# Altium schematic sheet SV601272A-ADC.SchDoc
size 431 x 279 mm; Date: Not shown in title block; ApprovedBy: Not shown in title block; CheckedBy: Not shown in title block; Author: Not shown in title block; CompanyName: Not shown in title block; Engineer: Not shown in title block; Organization: Not shown in title block; Address1: Not shown in title block; Address2: Not shown in title block; Address3: Not shown in title block; Address4: Not shown in title block; DocumentNumber: 9; Revision: Use project parameter SCH_Rev; SheetNumber: 9; SheetTotal: 11; PageSetup: Record=PageOptions¦CenterHorizontal=True¦CenterVertical=True¦PrintScale=1.00¦XCorrection=1.00¦YCorrection=1.00¦PrintKind=0¦BorderSize=5000000¦LeftOffset=0¦BottomOffset=0¦Orientation=2¦PaperLength=1000¦PaperWidth=1000¦Scale=100¦PaperSource=15¦PrintQuality=600¦MediaType=1¦DitherType=10¦PaperKind=Letter¦PrintScaleMode=1
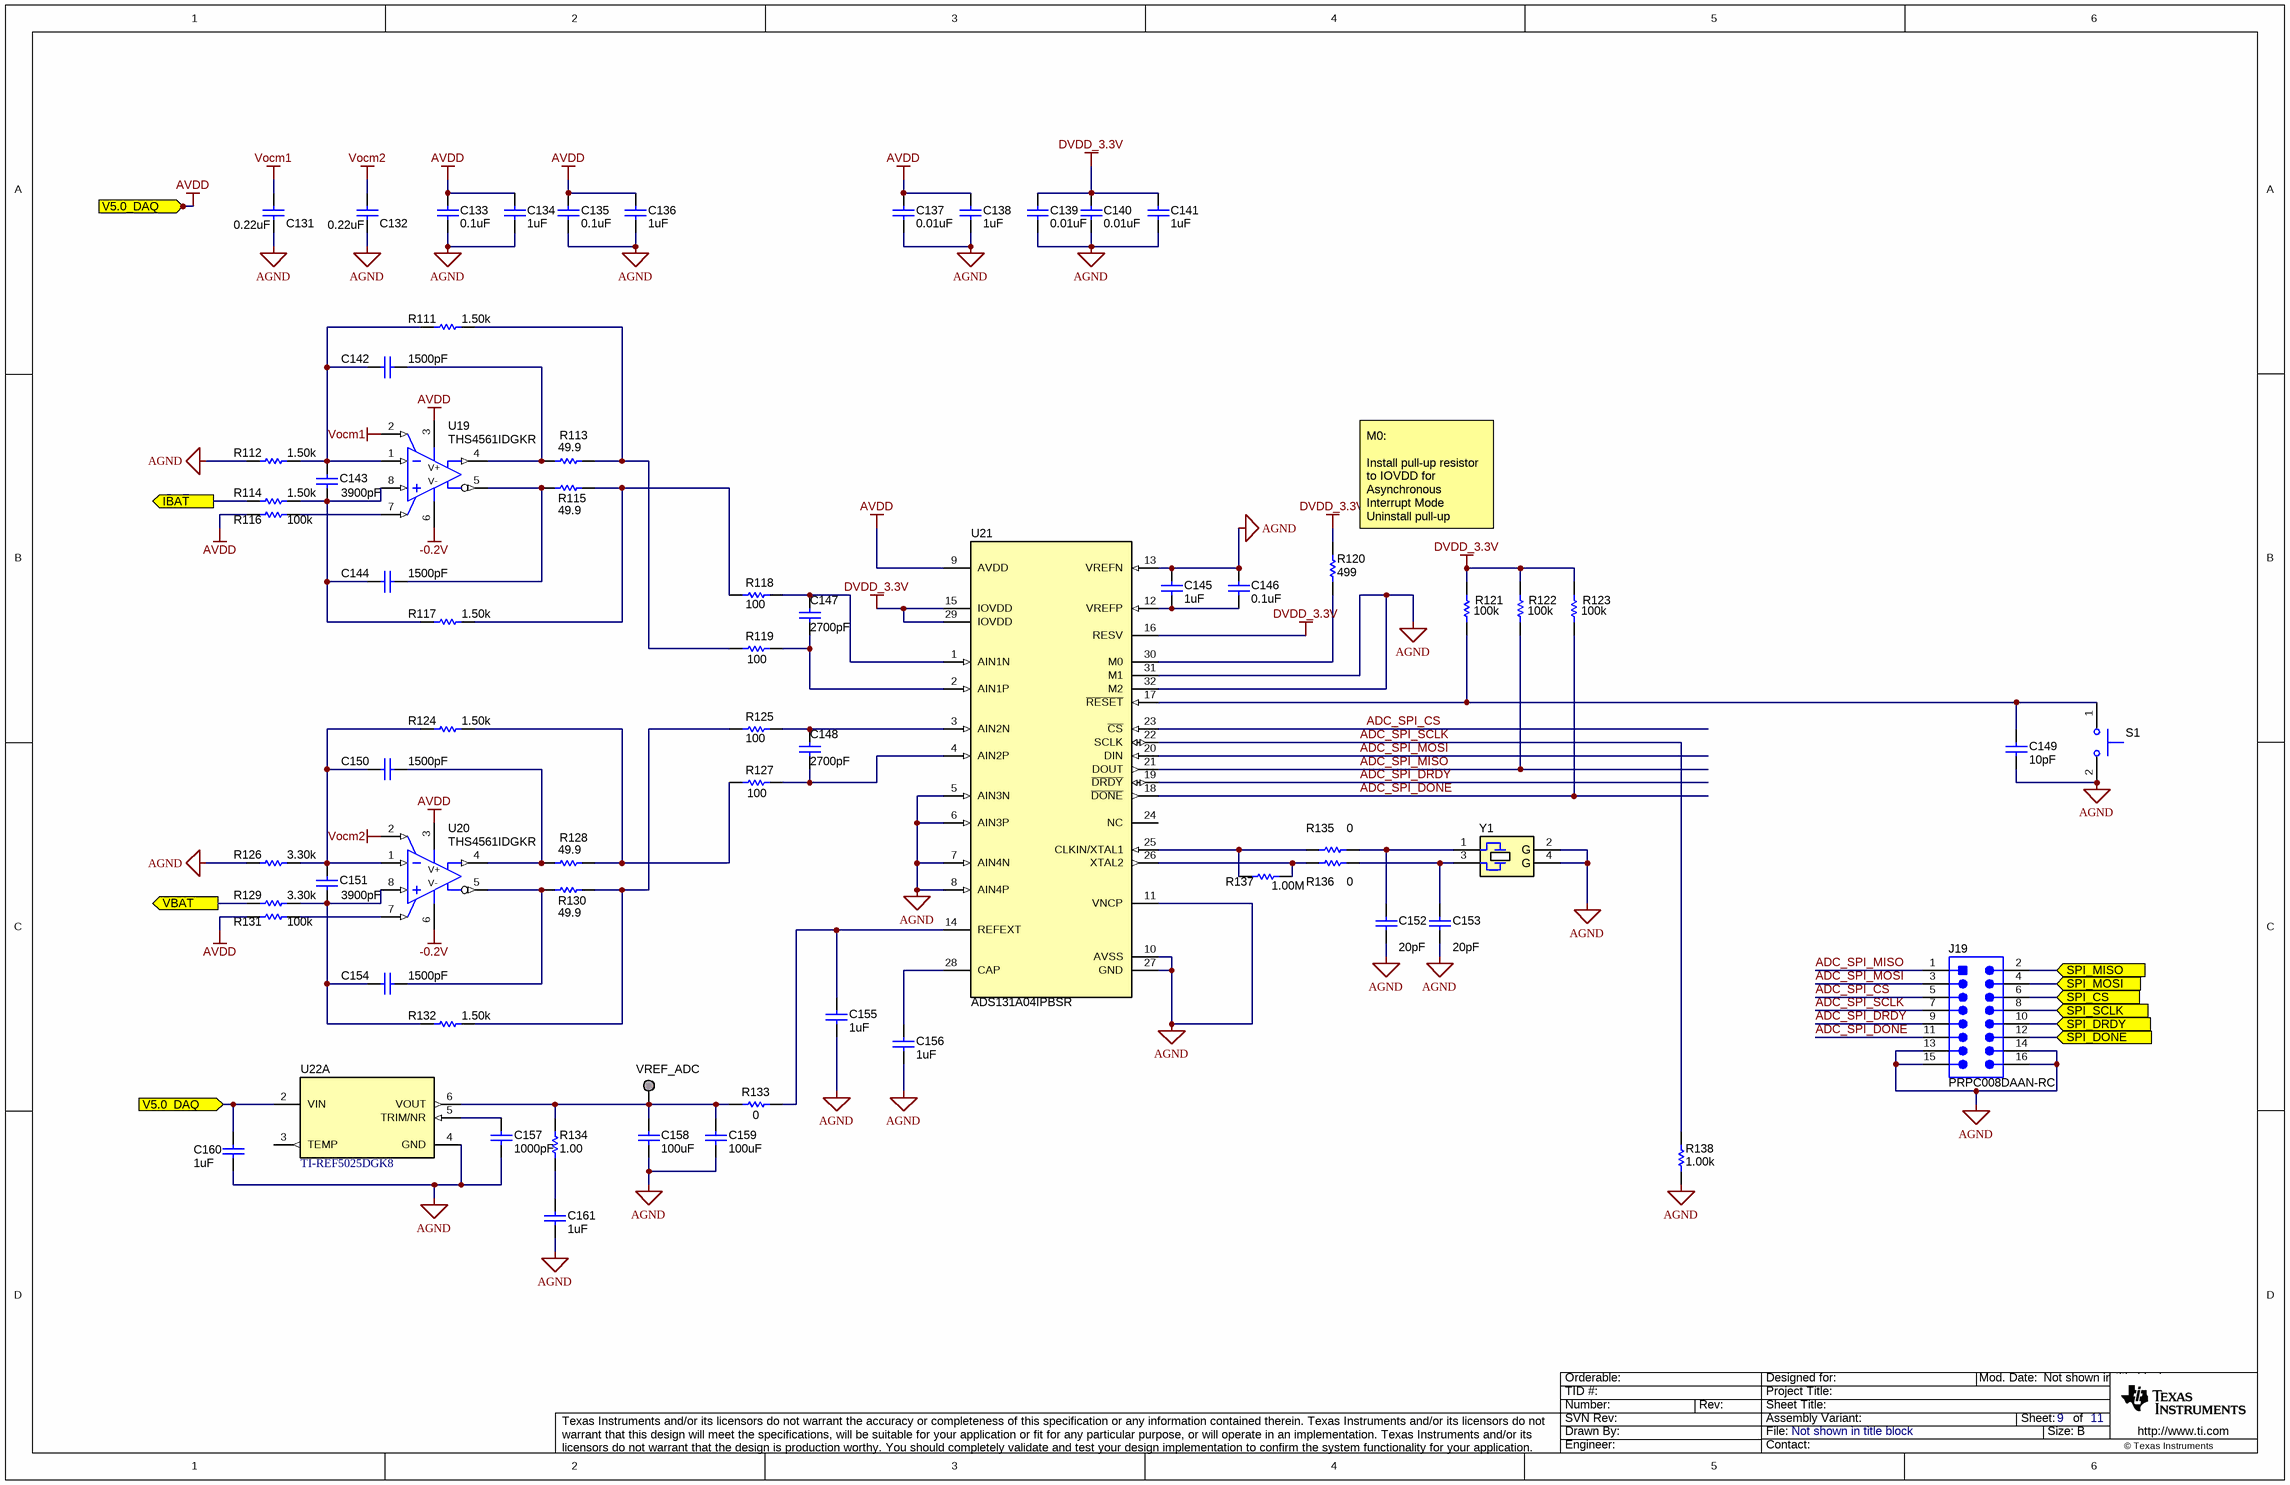
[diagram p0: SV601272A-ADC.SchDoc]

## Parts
C131  ValueDisplayed: 0.22uF  [0603]  (hidden comment: Capacitor)
C132  ValueDisplayed: 0.22uF  [0603]  (hidden comment: Capacitor)
C133  ValueDisplayed: 0.1uF  [0603]  (hidden comment: Capacitor)
C134  ValueDisplayed: 1uF  [0603]  (hidden comment: Capacitor)
C135  ValueDisplayed: 0.1uF  [0603]  (hidden comment: Capacitor)
C136  ValueDisplayed: 1uF  [0603]  (hidden comment: Capacitor)
C137  ValueDisplayed: 0.01uF  [0603]  (hidden comment: Capacitor)
C138  ValueDisplayed: 1uF  [0603]  (hidden comment: Capacitor)
C139  ValueDisplayed: 0.01uF  [0603]  (hidden comment: Capacitor)
C140  ValueDisplayed: 0.01uF  [0603]  (hidden comment: Capacitor)
C141  ValueDisplayed: 1uF  [0603]  (hidden comment: Capacitor)
C142  ValueDisplayed: 1500pF  [0603]  (hidden comment: Capacitor)
C143  ValueDisplayed: 3900pF  [0603]  (hidden comment: GRM188R72A392KA01D)
C144  ValueDisplayed: 1500pF  [0603]  (hidden comment: Capacitor)
C145  ValueDisplayed: 1uF  [0603]  (hidden comment: Capacitor)
C146  ValueDisplayed: 0.1uF  [0603]  (hidden comment: Capacitor)
C147  ValueDisplayed: 2700pF  [0603]  (hidden comment: Capacitor)
C148  ValueDisplayed: 2700pF  [0603]  (hidden comment: Capacitor)
C149  ValueDisplayed: 10pF  [0603]  (hidden comment: Capacitor)
C150  ValueDisplayed: 1500pF  [0603]  (hidden comment: Capacitor)
C151  ValueDisplayed: 3900pF  [0603]  (hidden comment: GRM188R72A392KA01D)
C152  ValueDisplayed: 20pF  [0603]  (hidden comment: GRM1885C1H200JA01D)
C153  ValueDisplayed: 20pF  [0603]  (hidden comment: GRM1885C1H200JA01D)
C154  ValueDisplayed: 1500pF  [0603]  (hidden comment: Capacitor)
C155  ValueDisplayed: 1uF  [0603]  (hidden comment: Capacitor)
C156  ValueDisplayed: 1uF  [0603]  (hidden comment: Capacitor)
C157  ValueDisplayed: 1000pF  [0603]  (hidden comment: Capacitor)
C158  ValueDisplayed: 100uF  [1206_190]  (hidden comment: Capacitor)
C159  ValueDisplayed: 100uF  [1206_190]  (hidden comment: Capacitor)
C160  ValueDisplayed: 1uF  [0603]  (hidden comment: Capacitor)
C161  ValueDisplayed: 1uF  [0603]  (hidden comment: Capacitor)
J19  PRPC008DAAN-RC  [Sullins_xxxC008DAAN]
R111  ValueDisplayed: 1.50k  [0603]  (hidden comment: RC0603FR-071K5L)
R112  ValueDisplayed: 1.50k  [0603]  (hidden comment: RC0603FR-071K5L)
R113  ValueDisplayed: 49.9  [0603]  (hidden comment: Resistor)
R114  ValueDisplayed: 1.50k  [0603]  (hidden comment: RC0603FR-071K5L)
R115  ValueDisplayed: 49.9  [0603]  (hidden comment: Resistor)
R116  ValueDisplayed: 100k  [0603]  (hidden comment: Resistor)
R117  ValueDisplayed: 1.50k  [0603]  (hidden comment: RC0603FR-071K5L)
R118  ValueDisplayed: 100  [0603]  (hidden comment: Resistor)
R119  ValueDisplayed: 100  [0603]  (hidden comment: Resistor)
R120  ValueDisplayed: 499  [0603]  (hidden comment: Resistor)
R121  ValueDisplayed: 100k  [0603]  (hidden comment: Resistor)
R122  ValueDisplayed: 100k  [0603]  (hidden comment: Resistor)
R123  ValueDisplayed: 100k  [0603]  (hidden comment: Resistor)
R124  ValueDisplayed: 1.50k  [0603]  (hidden comment: RC0603FR-071K5L)
R125  ValueDisplayed: 100  [0603]  (hidden comment: Resistor)
R126  ValueDisplayed: 3.30k  [0603]  (hidden comment: RC0603FR-073K3L)
R127  ValueDisplayed: 100  [0603]  (hidden comment: Resistor)
R128  ValueDisplayed: 49.9  [0603]  (hidden comment: Resistor)
R129  ValueDisplayed: 3.30k  [0603]  (hidden comment: RC0603FR-073K3L)
R130  ValueDisplayed: 49.9  [0603]  (hidden comment: Resistor)
R131  ValueDisplayed: 100k  [0603]  (hidden comment: Resistor)
R132  ValueDisplayed: 1.50k  [0603]  (hidden comment: RC0603FR-071K5L)
R133  ValueDisplayed: 0  [0603]  (hidden comment: Resistor)
R134  ValueDisplayed: 1.00  [0603]  (hidden comment: Resistor)
R135  ValueDisplayed: 0  [0603]  (hidden comment: Resistor)
R136  ValueDisplayed: 0  [0603]  (hidden comment: Resistor)
R137  ValueDisplayed: 1.00M  [0603]  (hidden comment: Resistor)
R138  ValueDisplayed: 1.00k  [0603]  (hidden comment: Resistor)
S1  Switch_PushButton  [SW_TL1015AF160QG]  (value not drawn)
U19  THS4561IDGKR  [DGK0008A_N]
U20  THS4561IDGKR  [DGK0008A_N]
U21  ADS131A04IPBSR  [PBS0032A_L]
U22  TI-REF5025DGK8  [DGK0008A_N]  (part A of 2)
VREF_ADC  Pogo Pad  [PogoPad]  (value not drawn)  (no BOM)
Y1  XTAL_4P_13_G24  [CTS_407]  (value not drawn)

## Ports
IBAT, SPI_CS, SPI_DONE, SPI_DRDY, SPI_MISO, SPI_MOSI, SPI_SCLK, V5.0_DAQ, VBAT

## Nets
-0.2V: U19.6(VS-) U20.6(VS-)
AGND: C131.2 C132.2 C133.2 C134.2 C135.2 C136.2 C137.2 C138.2 C139.2 C140.2 C141.2 C145.1 C146.1 C149.1 C152.2 C153.2 C155.2 C156.2 C157.2 C158.2 C159.2 C160.2 C161.2 J19.13 J19.14 J19.15 J19.16 R112.1 R126.1 R138.1 S1.2 U21.5(AIN3N) U21.6(AIN3P) U21.7(AIN4N) U21.8(AIN4P) U21.10(AVSS) U21.11(VNCP) U21.13(VREFN) U21.27(GND) U21.31(M1) U21.32(M2) U22.4(GND) Y1.2(GND) Y1.4(GND)
AVDD: C133.1 C134.1 C135.1 C136.1 C137.1 C138.1 C160.1 R116.2 R131.2 U19.3(VS+) U20.3(VS+) U21.9(AVDD) U22.2(VIN) ; port V5.0_DAQ
DVDD_3.3V: C139.1 C140.1 C141.1 R120.2 R121.2 R122.2 R123.2 U21.15(IOVDD) U21.16(RESV) U21.29(IOVDD)
Vocm1: C131.1 U19.2(VOCM)
Vocm2: C132.1 U20.2(VOCM)
ADC_SPI_CS: J19.5 U21.23(~{CS})
ADC_SPI_DONE: J19.11 R123.1 U21.18(~{DONE})
ADC_SPI_DRDY: J19.9 U21.19(~{DRDY})
ADC_SPI_MISO: J19.1 R122.1 U21.21(DOUT)
ADC_SPI_MOSI: J19.3 U21.20(DIN)
ADC_SPI_SCLK: J19.7 R138.2 U21.22(SCLK)
IBAT: R114.1 ; port IBAT
SPI_CS: J19.6 ; port SPI_CS
SPI_DONE: J19.12 ; port SPI_DONE
SPI_DRDY: J19.10 ; port SPI_DRDY
SPI_MISO: J19.2 ; port SPI_MISO
SPI_MOSI: J19.4 ; port SPI_MOSI
SPI_SCLK: J19.8 ; port SPI_SCLK
VBAT: R129.1 ; port VBAT
NetC142_1: C142.1 C143.1 R111.1 R112.2 U19.1(VIN-)
NetC142_2: C142.2 R113.1 U19.4(VOUT+)
NetC143_2: C143.2 C144.1 R114.2 R117.1 U19.8(VIN+)
NetC144_2: C144.2 R115.1 U19.5(VOUT-)
NetC145_2: C145.2 C146.2 U21.12(VREFP)
NetC147_1: C147.1 R118.2 U21.1(AIN1N)
NetC147_2: C147.2 R119.2 U21.2(AIN1P)
NetC148_1: C148.1 R125.2 U21.3(AIN2N)
NetC148_2: C148.2 R127.2 U21.4(AIN2P)
NetC149_2: C149.2 R121.1 S1.1 U21.17(~{RESET})
NetC150_1: C150.1 C151.1 R124.1 R126.2 U20.1(VIN-)
NetC150_2: C150.2 R128.1 U20.4(VOUT+)
NetC151_2: C151.2 C154.1 R129.2 R132.1 U20.8(VIN+)
NetC152_1: C152.1 R135.2 Y1.1
NetC153_1: C153.1 R136.1 Y1.3
NetC154_2: C154.2 R130.1 U20.5(VOUT-)
NetC155_1: C155.1 R133.2 U21.14(REFEXT)
NetC156_1: C156.1 U21.28(CAP)
NetC157_1: C157.1 U22.5(TRIM/NR)
NetC158_1: C158.1 C159.1 R133.1 R134.2 U22.6(VOUT) VREF_ADC.1
NetC161_1: C161.1 R134.1
NetR111_2: R111.2 R113.2 R119.1
NetR115_2: R115.2 R117.2 R118.1
NetR116_1: R116.1 U19.7(~{PD})
NetR120_1: R120.1 U21.30(M0)
NetR124_2: R124.2 R127.1 R128.2
NetR125_1: R125.1 R130.2 R132.2
NetR131_1: R131.1 U20.7(~{PD})
NetR135_1: R135.1 R137.2 U21.25(CLKIN/XTAL1)
NetR136_2: R136.2 R137.1 U21.26(XTAL2)

Not connected (* = marked no-connect by the designer): U21 24(NC); U22 3(TEMP)

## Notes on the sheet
- (near R120) M0:
  Install pull-up resistor to IOVDD for Asynchronous Interrupt Mode
  Uninstall pull-up resistor to leave M0 floating for Synchronous Slave Mode

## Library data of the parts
C131 C132 = CMP-0006903-4: CAP, CERM, 0.22 uF, 16 V, +/- 10%, X7R, 0603; PartNumber: C0603C224K4RACTU; Manufacturer: Kemet; Polarized: N; Value: 0.22uF; U/M: EA; Cap_F: 220nF; Value1: Unknown; VDC_V: 16V; TaMin_C: -55°C; TaMax_C: 125°C; AEC Category: Q200; SizeArea_mm2: 1.28; SizeAreaWB_mm2: 4.68; SizeX_mm: 1.6; SizeY_mm: 0.8; SizeZ_mm: 1
C133 C135 C146 = CMP-0006752-5: CAP, CERM, 0.1 uF, 25 V, +/- 5%, X7R, 0603; PartNumber: 06033C104JAT2A; Manufacturer: AVX; Polarized: N; Value: 0.1uF; U/M: EA; Cap_F: 100nF; ESR_ohm: 0.05; Value1: 0.05 ohm; VDC_V: 25V; TaMin_C: -55°C; TaMax_C: 125°C; AEC Category: Q200; SizeArea_mm2: 1.28; SizeAreaWB_mm2: 4.68; SizeX_mm: 1.6; SizeY_mm: 0.8; SizeZ_mm: 1
C134 C136 C138 C141 C145 C155 C156 C160 C161 = CMP-0007405-4: CAP, CERM, 1 uF, 25 V, +/- 10%, X7R, 0603; PartNumber: GRM188R71E105KA12D; Manufacturer: MuRata; Polarized: N; Value: 1uF; U/M: EA; Cap_F: 1µF; Value1: Unknown; VDC_V: 25V; TaMin_C: -55°C; TaMax_C: 125°C; AEC Category: Q200; SizeArea_mm2: 1.28; SizeAreaWB_mm2: 4.68; SizeX_mm: 1.6; SizeY_mm: 0.8; SizeZ_mm: 1
C137 C139 C140 = CMP-0006727-4: CAP, CERM, 0.01 uF, 100 V, +/- 10%, X7R, 0603; PartNumber: 06031C103KAT2A; Manufacturer: AVX; Polarized: N; Value: 0.01uF; U/M: EA; Cap_F: 10nF; ESR_ohm: 0.098; Value1: 0.098 ohm; VDC_V: 100V; TaMin_C: -55°C; TaMax_C: 125°C; AEC Category: Q200; SizeArea_mm2: 1.28; SizeAreaWB_mm2: 4.68; SizeX_mm: 1.6; SizeY_mm: 0.8; SizeZ_mm: 1
C142 C144 C150 C154 = CMP-0006732-4: CAP, CERM, 1500 pF, 100 V, +/- 5%, X7R, 0603; PartNumber: 06031C152JAT2A; Manufacturer: AVX; Polarized: N; Value: 1500pF; U/M: EA; Cap_F: 1.5nF; ESR_ohm: 2.29d; Value1: 0.229 ohm; VDC_V: 100V; TaMin_C: -55°C; TaMax_C: 125°C; AEC Category: Q200; SizeArea_mm2: 1.28; SizeAreaWB_mm2: 4.68; SizeX_mm: 1.6; SizeY_mm: 0.8; SizeZ_mm: 1
C143 C151 = CMP-0007481-5: CAP, CERM, 3900 pF, 100 V, +/- 10%, X7R, 0603; Manufacturer: MuRata; TaMin_C: -55°C; Polarized: N; SizeAreaWB_mm2: 4.68; Value1: Unknown; U/M: EA; Value: 3900pF; TaMax_C: 125°C; SizeZ_mm: 1; SizeX_mm: 1.6; SizeY_mm: 0.8; Value2: 100V; SizeArea_mm2: 1.28; CompType: Capacitor; Cap_F: 3.9nF; AEC Category: Q200
C147 C148 = CMP-0007204-4: CAP, CERM, 2700 pF, 50 V, +/- 5%, C0G/NP0, 0603; PartNumber: GRM1885C1H272JA01D; Manufacturer: MuRata; Polarized: N; Value: 2700pF; U/M: EA; Cap_F: 2.7nF; Value1: Unknown; VDC_V: 50V; TaMin_C: -55°C; TaMax_C: 125°C; AEC Category: Q200; SizeArea_mm2: 1.28; SizeAreaWB_mm2: 4.68; SizeX_mm: 1.6; SizeY_mm: 0.8; SizeZ_mm: 1
C149 = CMP-0006761-4: CAP, CERM, 10 pF, 50 V, +/- 5%, C0G/NP0, 0603; PartNumber: 06035A100JAT2A; Manufacturer: AVX; Polarized: N; Value: 10pF; U/M: EA; ESR_ohm: 4.03d; Value1: 0.403 ohm; VDC_V: 50V; TaMin_C: -55°C; TaMax_C: 125°C; AEC Category: Q200; SizeArea_mm2: 1.28; SizeAreaWB_mm2: 4.68; SizeX_mm: 1.6; SizeY_mm: 0.8; SizeZ_mm: 1
C152 C153 = CMP-0007193-4: CAP, CERM, 20 pF, 50 V, +/- 5%, C0G/NP0, 0603; Manufacturer: MuRata; TaMin_C: -55°C; Polarized: N; SizeAreaWB_mm2: 4.68; Value1: Unknown; U/M: EA; Value: 20pF; TaMax_C: 125°C; SizeZ_mm: 1; SizeX_mm: 1.6; SizeY_mm: 0.8; Value2: 50V; SizeArea_mm2: 1.28; CompType: Capacitor; AEC Category: Q200
C157 = CMP-0006723-4: CAP, CERM, 1000 pF, 100 V, +/- 5%, X7R, 0603; PartNumber: 06031C102JAT2A; Manufacturer: AVX; Polarized: N; Value: 1000pF; U/M: EA; Cap_F: 1nF; ESR_ohm: 2.76d; Value1: 0.276 ohm; VDC_V: 100V; TaMin_C: -55°C; TaMax_C: 125°C; AEC Category: Q200; SizeArea_mm2: 1.28; SizeAreaWB_mm2: 4.68; SizeX_mm: 1.6; SizeY_mm: 0.8; SizeZ_mm: 1
C158 C159 = CMP-0008649-2: CAP, CERM, 100 uF, 10 V, +/- 20%, X5R, 1206_190; PartNumber: C3216X5R1A107M160AC; Manufacturer: TDK; Polarized: N; Value: 100uF; U/M: EA; Cap_F: 100µF; ESR_ohm: 2.838m; Value1: 0.002838 ohm; VDC_V: 10V; IRMS_A: 4.30694A; TaMin_C: -55°C; TaMax_C: 85°C; AEC Category: Q200; SizeArea_mm2: 5.12; SizeAreaWB_mm2: 10.92; SizeX_mm: 3.2; SizeY_mm: 1.6; SizeZ_mm: 1.9
J19 = CMP-0054590-1: Header, 2.54mm, 8x2, Gold, TH; Manufacturer: Sullins Connector Solutions; CNHeader: TRUE; Shrouded: N; Gender: Male; Row_Count: 2; RowSpacing_mm: 2.54; CT: FALSE
R111 R112 R114 R117 R124 = CMP-0022883-3: RES, 1.50 k, 1%, 0.1 W, 0603; Manufacturer: Yageo America; Power_W: 100mW; TempCo: 200 ppm/C; Value_Code: 1k50; U/M: EA; Value: 1.50k; EIA_Code: E96; Res_ohm: 1.5k; SizeX_mm: 1.6; SizeY_mm: 0.8; SizeZ_mm: 1; Value2: 0.1W; SizeArea_mm2: 1.28; CompType: Resistor; VDC_V: 150V; AEC Category: Q200
R113 R115 R128 R130 = CMP-0022448-4: RES, 49.9, 1%, 0.1 W, AEC-Q200 Grade 0, 0603; PartNumber: CRCW060349R9FKEA; Manufacturer: Vishay-Dale; Value: 49.9; Value_Code: 49R9; Power_W: 100mW; Value2: 0.1W; VDC_V: 75V; TempCo: 100 ppm/C; EIA_Code: E96; AEC Category: Q200; AEC Qualified: Y; AEC Grade: 0; SizeArea_mm2: 1.28; SizeX_mm: 1.6; SizeY_mm: 0.8; SizeZ_mm: 1
R116 R121-R123 R131 = CMP-0021990-4: RES, 100 k, 1%, 0.1 W, AEC-Q200 Grade 0, 0603; PartNumber: CRCW0603100KFKEA; Manufacturer: Vishay-Dale; Value: 100k; Power_W: 100mW; Value2: 0.1W; VDC_V: 75V; TempCo: 100 ppm/C; EIA_Code: E96; AEC Category: Q200; AEC Qualified: Y; AEC Grade: 0; SizeArea_mm2: 1.28; SizeX_mm: 1.6; SizeY_mm: 0.8; SizeZ_mm: 1
R118 R119 R125 R127 = CMP-0021991-4: RES, 100, 1%, 0.1 W, AEC-Q200 Grade 0, 0603; PartNumber: CRCW0603100RFKEA; Manufacturer: Vishay-Dale; Value: 100; Value_Code: 100R; Power_W: 100mW; Value2: 0.1W; VDC_V: 75V; TempCo: 100 ppm/C; EIA_Code: E96; AEC Category: Q200; AEC Qualified: Y; AEC Grade: 0; SizeArea_mm2: 1.28; SizeX_mm: 1.6; SizeY_mm: 0.8; SizeZ_mm: 1
R120 = CMP-0022446-5: RES, 499, 1%, 0.1 W, AEC-Q200 Grade 0, 0603; PartNumber: CRCW0603499RFKEA; Manufacturer: Vishay-Dale; Value: 499; Value_Code: 499R; Power_W: 100mW; Value2: 0.1W; VDC_V: 75V; TempCo: 100 ppm/C; EIA_Code: E96; AEC Category: Q200; AEC Qualified: Y; AEC Grade: 0; SizeArea_mm2: 1.28; SizeX_mm: 1.6; SizeY_mm: 0.8; SizeZ_mm: 1
R126 R129 = CMP-0023081-3: RES, 3.30 k, 1%, 0.1 W, 0603; Manufacturer: Yageo America; Power_W: 100mW; TempCo: 200 ppm/C; Value_Code: 3k30; U/M: EA; Value: 3.30k; Res_ohm: 3.3k; SizeX_mm: 1.6; SizeY_mm: 0.8; SizeZ_mm: 1; Value2: 0.1W; SizeArea_mm2: 1.28; VDC_V: 150V; AEC Category: Q200
R132 = CMP-0022883-3: RES, 1.50 k, 1%, 0.1 W, 0603; Manufacturer: Yageo America; Power_W: 100mW; TempCo: 200 ppm/C; Value_Code: 1k50; U/M: EA; Value: 1.50k; EIA_Code: E96; Res_ohm: 1.5k; SizeX_mm: 1.6; SizeY_mm: 0.8; SizeZ_mm: 1; Value2: 0.1W; SizeArea_mm2: 1.28; VDC_V: 150V; AEC Category: Q200
R133 R135 R136 = CMP-0025874-3: RES, 0, 5%, 0.1 W, 0603; PartNumber: ERJ-3GEY0R00V; Manufacturer: Panasonic; Value: 0; Value_Code: 0000; Power_W: 100mW; Value2: 0.1W; VDC_V: 50V; TempCo: 600 ppm/C; EIA_Code: E24; U/M: EA; AEC Category: Q200; SizeArea_mm2: 1.28; SizeX_mm: 1.6; SizeY_mm: 0.8; SizeZ_mm: 1
R134 = CMP-0022170-4: RES, 1.00, 1%, 0.1 W, AEC-Q200 Grade 0, 0603; PartNumber: CRCW06031R00FKEA; Manufacturer: Vishay-Dale; Value: 1.00; Res_ohm: 1; Value_Code: 1R00; Power_W: 100mW; Value2: 0.1W; VDC_V: 75V; TempCo: 100 ppm/C; EIA_Code: E96; AEC Category: Q200; AEC Qualified: Y; AEC Grade: 0; SizeArea_mm2: 1.28; SizeX_mm: 1.6; SizeY_mm: 0.8
R137 = CMP-0022138-4: RES, 1.00 M, 1%, 0.1 W, AEC-Q200 Grade 0, 0603; PartNumber: CRCW06031M00FKEA; Manufacturer: Vishay-Dale; Value: 1.00Meg; Res_ohm: 1M; Value_Code: 1M00; Power_W: 100mW; Value2: 0.1W; VDC_V: 75V; TempCo: 100 ppm/C; EIA_Code: E96; AEC Category: Q200; AEC Qualified: Y; AEC Grade: 0; SizeArea_mm2: 1.28; SizeX_mm: 1.6; SizeY_mm: 0.8; SizeZ_mm: 1
R138 = CMP-0022109-5: RES, 1.00 k, 1%, 0.1 W, AEC-Q200 Grade 0, 0603; PartNumber: CRCW06031K00FKEA; Manufacturer: Vishay-Dale; Value: 1.00k; Res_ohm: 1k; Value_Code: 1k00; Power_W: 100mW; Value2: 0.1W; VDC_V: 75V; TempCo: 100 ppm/C; EIA_Code: E96; AEC Category: Q200; AEC Qualified: Y; AEC Grade: 0; SizeArea_mm2: 1.28; SizeX_mm: 1.6; SizeY_mm: 0.8; SizeZ_mm: 1
S1 = CMP-0002143-3: Switch, Tactile, SPST-NO, 0.05A, 12V, SMT; PartNumber: TL1015AF160QG; Manufacturer: E-Switch; SwitchFunction: Off-Mom; PositionCount: 1; CurrentRating_mA: 50A
U19 U20 = CMP-0074888-1: Low-Power, High Supply Range, 60-MHz, Fully Differential Amplifier, DGK0008A (VSSOP-8); Alternate PartNumber: THS4561IDGKT; Alternate Manufacturer: Texas Instruments; SizeAreaWB_mm2: 35.955; U/M: EA; SizeZ_mm: 1.1; SizeX_mm: 5.05; SizeY_mm: 3.1; SizeArea_mm2: 15.655; CompType: IC
U21 = CMP-0075938-2: 24-Bit, 128kSPS, 4-Ch, Simultaneous Sampling, Delta-Sigma ADC, PBS0032A (TQFP-32); Manufacturer: Texas Instruments; SizeZ_mm: 1.2; SizeX_mm: 7.0; SizeArea_mm2: 49.0; CompType: IC; U/M: EA; SizeAreaWB_mm2: 81.0
U22 = CMP-0032584-1: Low Noise, Very Low Drift, Precision Voltage Reference, -40 to 125 degC, 8-pin MSOP(DGK), Green (RoHS & no Sb/Br); PartNumber: REF5025IDGKR; Manufacturer: Texas Instruments; Initial Accuracy @ 25/deg C(%): 0.05; Iout/Iz(Max)(mA): 10; Iq(Max)(uA): 1000; Rating: Military; SubFamily: Series Voltage Reference; Temp Coeff(Max)(ppm/ degree C): 3; VI(Max)(V): 18; VI(Min)(V): 2.7; VO(V): 2.5
VREF_ADC = PogoPad: Pad for Pogo Pin Connector; SymbolCreator: codlsc
Y1 = CMP-0004606-3: Crystal, 16.384 MHz, 20 pF, SMD; PartNumber: 407F35E016M3840; Manufacturer: CTS Electrocomponents; TaMin_C: -20°C; TaMax_C: 70°C; Frequency Stability: +/-50ppm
